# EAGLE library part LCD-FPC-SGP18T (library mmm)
LCD FPC-SGP18T Lcd screen 1.8" 128x160 Lien vendeur: Ebay womarts
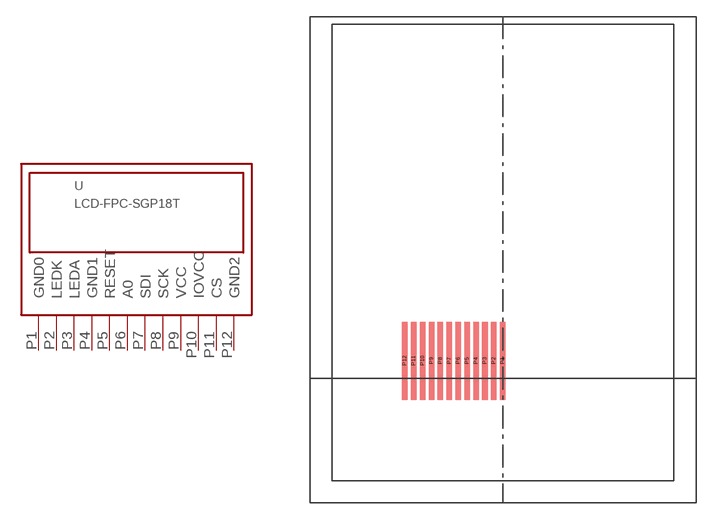
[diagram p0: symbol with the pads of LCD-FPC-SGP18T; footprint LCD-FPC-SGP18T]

Designator prefix -

## LCD-FPC-SGP18T  [LCD-FPC-SGP18T]
P1  GND0  pas
P2  LEDK  pas
P3  LEDA  pas
P4  GND1  pas
P5  RESET  in
P6  A0  in
P7  SDI
P8  SCK  in
P9  VCC  pas
P10  IOVCC  pas
P11  CS  in
P12  GND2  pas

## Footprint LCD-FPC-SGP18T (pad centres in mm)
smd 0.5 x 7: P1 0,1.6; P2 -0.8,1.6; P3 -1.6,1.6; P4 -2.4,1.6; P5 -3.2,1.6; P6 -4,1.6; P7 -4.8,1.6; P8 -5.6,1.6; P9 -6.4,1.6; P10 -7.2,1.6; P11 -8,1.6; P12 -8.8,1.6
